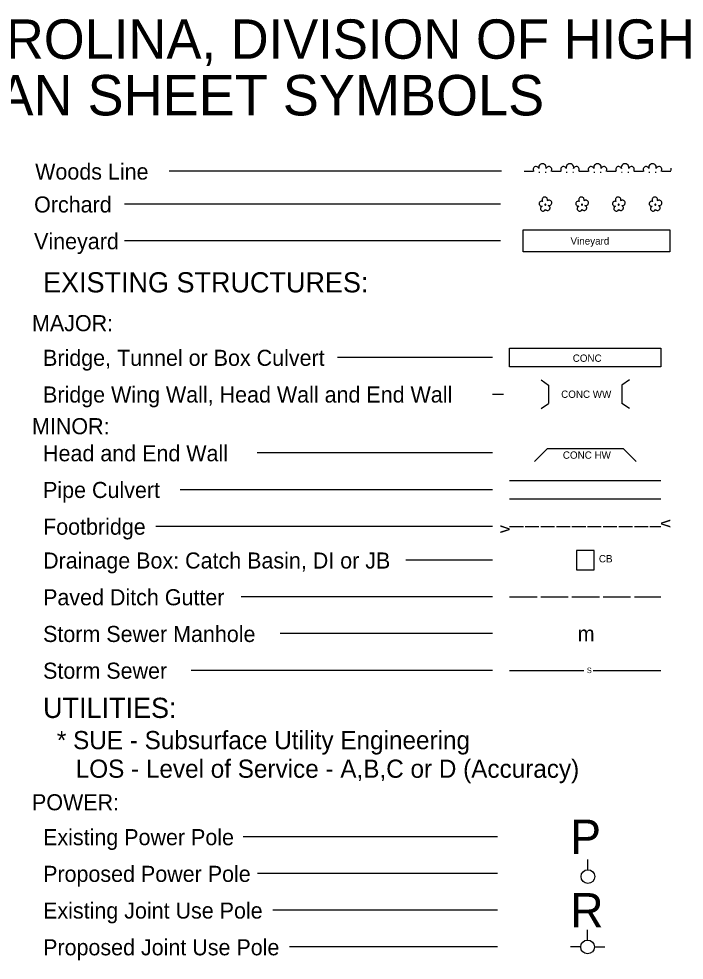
# Model space of a CAD drawing. Extents: x 2058324 to 2059808, y 675202 to 676238.
# Drawn here: x 2059088 to 2059451, y 675725 to 676238 of the extents above; entities that cross this region are included whole.
import ezdxf

# ---------------------------------------------------------------- set-up
doc = ezdxf.new("R2010")
doc.units = 0
doc.layers.add('Sheet Symbology CELL', color=7, linetype='Continuous')

msp = doc.modelspace()

# ---------------------------------------------------------------- linework, layer by layer
at = {"layer": 'Sheet Symbology CELL'}
for p, q in [((2059351.11, 676154.81), (2059169.98, 676154.81)), ((2059363.5, 676154.81), (2059368.5, 676154.81)), ((2059378.5, 676154.81), (2059383.5, 676154.81)), ((2059393.5, 676154.81), (2059398.5, 676154.81)), ((2059408.5, 676154.81), (2059413.5, 676154.81)), ((2059423.5, 676154.81), (2059428.5, 676154.81)), ((2059438.5, 676154.81), (2059443.5, 676154.81)), ((2059371.45, 676154.31), (2059371.95, 676154.31)), ((2059374.95, 676154.31), (2059375.45, 676154.31)), ((2059386.45, 676154.31), (2059386.95, 676154.31)), ((2059389.95, 676154.31), (2059390.45, 676154.31)), ((2059401.45, 676154.31), (2059401.95, 676154.31)), ((2059404.95, 676154.31), (2059405.45, 676154.31)), ((2059416.45, 676154.31), (2059416.95, 676154.31)), ((2059419.95, 676154.31), (2059420.45, 676154.31)), ((2059431.45, 676154.31), (2059431.95, 676154.31)), ((2059434.95, 676154.31), (2059435.45, 676154.31)), ((2059350.54, 676136.88), (2059145.6, 676136.88)), ((2059350.54, 676116.88), (2059145.6, 676116.88)), ((2059346.23, 676053.38), (2059261.8, 676053.38)), ((2059372.68, 676041.24), (2059376.78, 676038.38)), ((2059376.78, 676038.38), (2059376.78, 676028.38)), ((2059420.88, 676041.24), (2059416.78, 676038.38)), ((2059416.78, 676038.38), (2059416.78, 676028.38)), ((2059346.23, 676033.38), (2059352.21, 676033.38)), ((2059372.68, 676025.52), (2059376.78, 676028.38)), ((2059420.88, 676025.52), (2059416.78, 676028.38)), ((2059346.23, 676001.38), (2059217.93, 676001.38)), ((2059369.08, 675996.81), (2059376.15, 676003.88)), ((2059376.15, 676003.88), (2059417.4, 676003.88)), ((2059417.4, 676003.88), (2059424.48, 675996.81)), ((2059355.53, 675986.38), (2059438.03, 675986.38)), ((2059346.23, 675981.38), (2059176.04, 675981.38)), ((2059355.53, 675976.38), (2059438.03, 675976.38)), ((2059346.23, 675961.38), (2059162.75, 675961.38)), ((2059355.53, 675961.38), (2059363.03, 675961.38)), ((2059364.03, 675961.38), (2059371.53, 675961.38)), ((2059372.53, 675961.38), (2059380.03, 675961.38)), ((2059381.03, 675961.38), (2059388.53, 675961.38)), ((2059389.53, 675961.38), (2059397.03, 675961.38)), ((2059398.03, 675961.38), (2059405.53, 675961.38)), ((2059406.53, 675961.38), (2059414.03, 675961.38)), ((2059415.03, 675961.38), (2059422.53, 675961.38)), ((2059423.53, 675961.38), (2059431.03, 675961.38)), ((2059432.03, 675961.38), (2059438.03, 675961.38)), ((2059346.23, 675942.95), (2059299.03, 675942.95)), ((2059346.23, 675922.95), (2059209.28, 675922.95)), ((2059355.53, 675922.95), (2059370.53, 675922.95)), ((2059372.53, 675922.95), (2059387.53, 675922.95)), ((2059389.53, 675922.95), (2059404.53, 675922.95)), ((2059406.53, 675922.95), (2059421.53, 675922.95)), ((2059423.53, 675922.95), (2059438.03, 675922.95)), ((2059346.23, 675902.95), (2059230.55, 675902.95)), ((2059346.23, 675882.95), (2059182.03, 675882.95)), ((2059355.53, 675882.95), (2059396.05, 675882.95)), ((2059401.05, 675882.95), (2059438.03, 675882.95)), ((2059349.01, 675792.27), (2059210.31, 675792.27)), ((2059398.24, 675774.38), (2059398.24, 675780)), ((2059349.01, 675772.27), (2059218.1, 675772.27)), ((2059349.01, 675752.27), (2059226.5, 675752.27)), ((2059398.03, 675736.03), (2059398.03, 675741.65)), ((2059349.01, 675732.27), (2059235.5, 675732.27)), ((2059394.28, 675732.28), (2059388.65, 675732.28)), ((2059401.78, 675732.28), (2059407.4, 675732.28))]:
    msp.add_line(p, q, dxfattribs=at)
for points in [[(2059375.98, 676138.63), (2059376.13, 676138.93), (2059376.18, 676139.23), (2059376.13, 676139.53), (2059376.08, 676139.83), (2059375.93, 676140.08), (2059375.78, 676140.33), (2059375.53, 676140.53), (2059375.28, 676140.68), (2059374.93, 676140.78), (2059374.68, 676140.78), (2059374.38, 676140.73), (2059374.08, 676140.63), (2059373.83, 676140.48), (2059373.58, 676140.28), (2059373.43, 676139.98), (2059373.33, 676139.73), (2059373.28, 676139.43), (2059373.28, 676139.13), (2059373.33, 676138.83), (2059373.48, 676138.58), (2059373.68, 676138.28), (2059373.43, 676138.43), (2059373.13, 676138.48), (2059372.83, 676138.48), (2059372.58, 676138.38), (2059372.33, 676138.28), (2059372.08, 676138.08), (2059371.88, 676137.88), (2059371.73, 676137.63), (2059371.68, 676137.38), (2059371.63, 676137.03), (2059371.68, 676136.78), (2059371.78, 676136.53), (2059371.98, 676136.28), (2059372.13, 676136.08), (2059372.38, 676135.93), (2059372.68, 676135.78), (2059372.93, 676135.73), (2059373.23, 676135.73), (2059372.98, 676135.63), (2059372.73, 676135.43), (2059372.58, 676135.23), (2059372.48, 676134.93), (2059372.38, 676134.63), (2059372.38, 676134.38), (2059372.43, 676134.08), (2059372.58, 676133.83), (2059372.73, 676133.58), (2059372.93, 676133.38), (2059373.18, 676133.23), (2059373.43, 676133.13), (2059373.73, 676133.13), (2059374.03, 676133.13), (2059374.28, 676133.18), (2059374.53, 676133.38), (2059374.78, 676133.53), (2059375.03, 676133.98)], [(2059375.03, 676133.98), (2059375.63, 676133.63), (2059375.93, 676133.53), (2059376.23, 676133.48), (2059376.53, 676133.53), (2059376.78, 676133.63), (2059377.03, 676133.78), (2059377.28, 676133.98), (2059377.43, 676134.23), (2059377.53, 676134.48), (2059377.63, 676134.78), (2059377.58, 676135.08), (2059377.53, 676135.38), (2059377.33, 676135.68), (2059377.18, 676135.88), (2059376.93, 676136.03), (2059376.63, 676136.18), (2059376.93, 676136.13), (2059377.28, 676136.13), (2059377.53, 676136.23), (2059377.83, 676136.38), (2059378.08, 676136.53), (2059378.28, 676136.78), (2059378.43, 676137.08), (2059378.48, 676137.38), (2059378.53, 676137.68), (2059378.48, 676137.98), (2059378.38, 676138.28), (2059378.18, 676138.53), (2059377.93, 676138.78), (2059377.68, 676138.93), (2059377.38, 676139.03), (2059377.08, 676139.08), (2059376.78, 676139.08), (2059376.48, 676138.98), (2059376.23, 676138.83), (2059375.98, 676138.63)], [(2059395.98, 676138.63), (2059396.13, 676138.93), (2059396.18, 676139.23), (2059396.13, 676139.53), (2059396.08, 676139.83), (2059395.93, 676140.08), (2059395.78, 676140.33), (2059395.53, 676140.53), (2059395.28, 676140.68), (2059394.93, 676140.78), (2059394.68, 676140.78), (2059394.38, 676140.73), (2059394.08, 676140.63), (2059393.83, 676140.48), (2059393.58, 676140.28), (2059393.43, 676139.98), (2059393.33, 676139.73), (2059393.28, 676139.43), (2059393.28, 676139.13), (2059393.33, 676138.83), (2059393.48, 676138.58), (2059393.68, 676138.28), (2059393.43, 676138.43), (2059393.13, 676138.48), (2059392.83, 676138.48), (2059392.58, 676138.38), (2059392.33, 676138.28), (2059392.08, 676138.08), (2059391.88, 676137.88), (2059391.73, 676137.63), (2059391.68, 676137.38), (2059391.63, 676137.03), (2059391.68, 676136.78), (2059391.78, 676136.53), (2059391.98, 676136.28), (2059392.13, 676136.08), (2059392.38, 676135.93), (2059392.68, 676135.78), (2059392.93, 676135.73), (2059393.23, 676135.73), (2059392.98, 676135.63), (2059392.73, 676135.43), (2059392.58, 676135.23), (2059392.48, 676134.93), (2059392.38, 676134.63), (2059392.38, 676134.38), (2059392.43, 676134.08), (2059392.58, 676133.83), (2059392.73, 676133.58), (2059392.93, 676133.38), (2059393.18, 676133.23), (2059393.43, 676133.13), (2059393.73, 676133.13), (2059394.03, 676133.13), (2059394.28, 676133.18), (2059394.53, 676133.38), (2059394.78, 676133.53), (2059395.03, 676133.98)], [(2059395.03, 676133.98), (2059395.63, 676133.63), (2059395.93, 676133.53), (2059396.23, 676133.48), (2059396.53, 676133.53), (2059396.78, 676133.63), (2059397.03, 676133.78), (2059397.28, 676133.98), (2059397.43, 676134.23), (2059397.53, 676134.48), (2059397.63, 676134.78), (2059397.58, 676135.08), (2059397.53, 676135.38), (2059397.33, 676135.68), (2059397.18, 676135.88), (2059396.93, 676136.03), (2059396.63, 676136.18), (2059396.93, 676136.13), (2059397.28, 676136.13), (2059397.53, 676136.23), (2059397.83, 676136.38), (2059398.08, 676136.53), (2059398.28, 676136.78), (2059398.43, 676137.08), (2059398.48, 676137.38), (2059398.53, 676137.68), (2059398.48, 676137.98), (2059398.38, 676138.28), (2059398.18, 676138.53), (2059397.93, 676138.78), (2059397.68, 676138.93), (2059397.38, 676139.03), (2059397.08, 676139.08), (2059396.78, 676139.08), (2059396.48, 676138.98), (2059396.23, 676138.83), (2059395.98, 676138.63)], [(2059415.98, 676138.63), (2059416.13, 676138.93), (2059416.18, 676139.23), (2059416.13, 676139.53), (2059416.08, 676139.83), (2059415.93, 676140.08), (2059415.78, 676140.33), (2059415.53, 676140.53), (2059415.28, 676140.68), (2059414.93, 676140.78), (2059414.68, 676140.78), (2059414.38, 676140.73), (2059414.08, 676140.63), (2059413.83, 676140.48), (2059413.58, 676140.28), (2059413.43, 676139.98), (2059413.33, 676139.73), (2059413.28, 676139.43), (2059413.28, 676139.13), (2059413.33, 676138.83), (2059413.48, 676138.58), (2059413.68, 676138.28), (2059413.43, 676138.43), (2059413.13, 676138.48), (2059412.83, 676138.48), (2059412.58, 676138.38), (2059412.33, 676138.28), (2059412.08, 676138.08), (2059411.88, 676137.88), (2059411.73, 676137.63), (2059411.68, 676137.38), (2059411.63, 676137.03), (2059411.68, 676136.78), (2059411.78, 676136.53), (2059411.98, 676136.28), (2059412.13, 676136.08), (2059412.38, 676135.93), (2059412.68, 676135.78), (2059412.93, 676135.73), (2059413.23, 676135.73), (2059412.98, 676135.63), (2059412.73, 676135.43), (2059412.58, 676135.23), (2059412.48, 676134.93), (2059412.38, 676134.63), (2059412.38, 676134.38), (2059412.43, 676134.08), (2059412.58, 676133.83), (2059412.73, 676133.58), (2059412.93, 676133.38), (2059413.18, 676133.23), (2059413.43, 676133.13), (2059413.73, 676133.13), (2059414.03, 676133.13), (2059414.28, 676133.18), (2059414.53, 676133.38), (2059414.78, 676133.53), (2059415.03, 676133.98)], [(2059415.03, 676133.98), (2059415.63, 676133.63), (2059415.93, 676133.53), (2059416.23, 676133.48), (2059416.53, 676133.53), (2059416.78, 676133.63), (2059417.03, 676133.78), (2059417.28, 676133.98), (2059417.43, 676134.23), (2059417.53, 676134.48), (2059417.63, 676134.78), (2059417.58, 676135.08), (2059417.53, 676135.38), (2059417.33, 676135.68), (2059417.18, 676135.88), (2059416.93, 676136.03), (2059416.63, 676136.18), (2059416.93, 676136.13), (2059417.28, 676136.13), (2059417.53, 676136.23), (2059417.83, 676136.38), (2059418.08, 676136.53), (2059418.28, 676136.78), (2059418.43, 676137.08), (2059418.48, 676137.38), (2059418.53, 676137.68), (2059418.48, 676137.98), (2059418.38, 676138.28), (2059418.18, 676138.53), (2059417.93, 676138.78), (2059417.68, 676138.93), (2059417.38, 676139.03), (2059417.08, 676139.08), (2059416.78, 676139.08), (2059416.48, 676138.98), (2059416.23, 676138.83), (2059415.98, 676138.63)], [(2059435.98, 676138.63), (2059436.13, 676138.93), (2059436.18, 676139.23), (2059436.13, 676139.53), (2059436.08, 676139.83), (2059435.93, 676140.08), (2059435.78, 676140.33), (2059435.53, 676140.53), (2059435.28, 676140.68), (2059434.93, 676140.78), (2059434.68, 676140.78), (2059434.38, 676140.73), (2059434.08, 676140.63), (2059433.83, 676140.48), (2059433.58, 676140.28), (2059433.43, 676139.98), (2059433.33, 676139.73), (2059433.28, 676139.43), (2059433.28, 676139.13), (2059433.33, 676138.83), (2059433.48, 676138.58), (2059433.68, 676138.28), (2059433.43, 676138.43), (2059433.13, 676138.48), (2059432.83, 676138.48), (2059432.58, 676138.38), (2059432.33, 676138.28), (2059432.08, 676138.08), (2059431.88, 676137.88), (2059431.73, 676137.63), (2059431.68, 676137.38), (2059431.63, 676137.03), (2059431.68, 676136.78), (2059431.78, 676136.53), (2059431.98, 676136.28), (2059432.13, 676136.08), (2059432.38, 676135.93), (2059432.68, 676135.78), (2059432.93, 676135.73), (2059433.23, 676135.73), (2059432.98, 676135.63), (2059432.73, 676135.43), (2059432.58, 676135.23), (2059432.48, 676134.93), (2059432.38, 676134.63), (2059432.38, 676134.38), (2059432.43, 676134.08), (2059432.58, 676133.83), (2059432.73, 676133.58), (2059432.93, 676133.38), (2059433.18, 676133.23), (2059433.43, 676133.13), (2059433.73, 676133.13), (2059434.03, 676133.13), (2059434.28, 676133.18), (2059434.53, 676133.38), (2059434.78, 676133.53), (2059435.03, 676133.98)], [(2059435.03, 676133.98), (2059435.63, 676133.63), (2059435.93, 676133.53), (2059436.23, 676133.48), (2059436.53, 676133.53), (2059436.78, 676133.63), (2059437.03, 676133.78), (2059437.28, 676133.98), (2059437.43, 676134.23), (2059437.53, 676134.48), (2059437.63, 676134.78), (2059437.58, 676135.08), (2059437.53, 676135.38), (2059437.33, 676135.68), (2059437.18, 676135.88), (2059436.93, 676136.03), (2059436.63, 676136.18), (2059436.93, 676136.13), (2059437.28, 676136.13), (2059437.53, 676136.23), (2059437.83, 676136.38), (2059438.08, 676136.53), (2059438.28, 676136.78), (2059438.43, 676137.08), (2059438.48, 676137.38), (2059438.53, 676137.68), (2059438.48, 676137.98), (2059438.38, 676138.28), (2059438.18, 676138.53), (2059437.93, 676138.78), (2059437.68, 676138.93), (2059437.38, 676139.03), (2059437.08, 676139.08), (2059436.78, 676139.08), (2059436.48, 676138.98), (2059436.23, 676138.83), (2059435.98, 676138.63)], [(2059375.13, 676136.88), (2059374.98, 676136.88), (2059374.88, 676136.83), (2059374.78, 676136.78), (2059374.78, 676136.63), (2059374.78, 676136.53), (2059374.88, 676136.43), (2059375.03, 676136.43), (2059375.13, 676136.43), (2059375.23, 676136.53), (2059375.28, 676136.68), (2059375.23, 676136.78), (2059375.13, 676136.88)], [(2059395.13, 676136.88), (2059394.98, 676136.88), (2059394.88, 676136.83), (2059394.78, 676136.78), (2059394.78, 676136.63), (2059394.78, 676136.53), (2059394.88, 676136.43), (2059395.03, 676136.43), (2059395.13, 676136.43), (2059395.23, 676136.53), (2059395.28, 676136.68), (2059395.23, 676136.78), (2059395.13, 676136.88)], [(2059415.13, 676136.88), (2059414.98, 676136.88), (2059414.88, 676136.83), (2059414.78, 676136.78), (2059414.78, 676136.63), (2059414.78, 676136.53), (2059414.88, 676136.43), (2059415.03, 676136.43), (2059415.13, 676136.43), (2059415.23, 676136.53), (2059415.28, 676136.68), (2059415.23, 676136.78), (2059415.13, 676136.88)], [(2059435.13, 676136.88), (2059434.98, 676136.88), (2059434.88, 676136.83), (2059434.78, 676136.78), (2059434.78, 676136.63), (2059434.78, 676136.53), (2059434.88, 676136.43), (2059435.03, 676136.43), (2059435.13, 676136.43), (2059435.23, 676136.53), (2059435.28, 676136.68), (2059435.23, 676136.78), (2059435.13, 676136.88)], [(2059362.93, 676122.88), (2059442.93, 676122.88), (2059442.93, 676110.88), (2059362.93, 676110.88), (2059362.93, 676122.88)], [(2059355.53, 676058.38), (2059438.03, 676058.38), (2059438.03, 676048.38), (2059355.53, 676048.38), (2059355.53, 676058.38)]]:
    msp.add_lwpolyline(points, dxfattribs=at)
msp.add_lwpolyline([(2059391.96, 675937.63), (2059401.58, 675937.63), (2059401.58, 675948.27), (2059391.96, 675948.27)], close=True, dxfattribs=at)
for centre in [(2059398.24, 675770.63), (2059398.03, 675732.27)]:
    msp.add_circle(centre, 3.75, dxfattribs=at)
for centre, radius, start, end in [((2059369.95, 676155.83), 1.58, 18.4349, 219.2315), ((2059373.45, 676156.83), 2.06, 345.9638, 194.0362), ((2059376.95, 676155.83), 1.58, 320.7685, 161.565), ((2059384.95, 676155.83), 1.58, 18.4349, 219.2315), ((2059388.45, 676156.83), 2.06, 345.9638, 194.0362), ((2059391.95, 676155.83), 1.58, 320.7685, 161.565), ((2059399.95, 676155.83), 1.58, 18.4349, 219.2315), ((2059403.45, 676156.83), 2.06, 345.9638, 194.0362), ((2059406.95, 676155.83), 1.58, 320.7685, 161.565), ((2059414.95, 676155.83), 1.58, 18.4349, 219.2315), ((2059418.45, 676156.83), 2.06, 345.9638, 194.0362), ((2059421.95, 676155.83), 1.58, 320.7685, 161.565), ((2059429.95, 676155.83), 1.58, 18.4349, 219.2315), ((2059433.45, 676156.83), 2.06, 345.9638, 194.0362), ((2059436.95, 676155.83), 1.58, 320.7685, 161.565), ((2059444.95, 676155.83), 1.58, 156.251, 203.749)]:
    msp.add_arc(centre, radius, start, end, dxfattribs=at)

# ---------------------------------------------------------------- texts
for s, height, rotation, p in [('STATE OF NORTH CAROLINA, DIVISION OF HIGHWAYS', 21.419, 360, (2058783.41, 676216.12)), ('CONVENTIONAL  PLAN SHEET SYMBOLS', 22.0323, 360, (2058791.54, 676185.24)), ('Woods Line', 8.75, 360, (2059096.95, 676150.29)), ('Orchard', 8.75, 360, (2059096.38, 676132.36)), ('Vineyard', 8.75, 360, (2059096.38, 676112.36)), ('Vineyard', 4, 0, (2059388.76, 676114.88)), ('EXISTING STRUCTURES:', 11, 360, (2059101.26, 676088.83)), ('MAJOR:', 8.75, 360, (2059095.24, 676067.71)), ('Bridge, Tunnel or Box Culvert', 8.75, 360, (2059101.26, 676048.83)), ('CONC', 4, 360, (2059389.96, 676051.02)), ('Bridge Wing Wall, Head Wall and End Wall', 8.75, 360, (2059101.26, 676028.83)), ('CONC WW', 4, 0, (2059383.65, 676031.38)), ('MINOR:', 8.75, 360, (2059095.24, 676011.59)), ('Head and End Wall', 8.75, 360, (2059101.26, 675996.83)), ('CONC HW', 4, 360, (2059384.58, 675998.22)), ('Pipe Culvert', 8.75, 360, (2059101.26, 675976.85)), ('Footbridge', 8.75, 360, (2059101.28, 675956.85)), ('v', 6.6, 270.2409, (2059438.01, 675965.12)), ('v', 6.6, 89.7591, (2059355.51, 675957.65)), ('Drainage Box: Catch Basin, DI or JB', 8.75, 360, (2059101.28, 675938.41)), ('CB', 4, 360, (2059404.21, 675941.77)), ('Paved Ditch Gutter', 8.75, 360, (2059101.28, 675918.4)), ('Storm Sewer Manhole', 8.75, 360, (2059101.28, 675898.4)), ('m', 8.25, 360, (2059392.65, 675898.82)), ('Storm Sewer', 8.75, 360, (2059101.28, 675878.4)), ('S', 3, 360, (2059397.65, 675881.45)), ('UTILITIES:', 11, 360, (2059101.26, 675857.03)), ('* SUE - Subsurface Utility Engineering', 9.9, 360, (2059108.8, 675840.01)), ('LOS - Level of Service - A,B,C or D (Accuracy) ', 9.9, 360, (2059119.07, 675824.44)), ('POWER:', 8.75, 360, (2059095.24, 675806.73)), ('P', 18.75, 360, (2059388.65, 675782.89)), ('Existing Power Pole', 8.75, 360, (2059101.28, 675787.73)), ('Proposed Power Pole', 8.75, 360, (2059101.28, 675767.73)), ('R', 18.75, 360, (2059388.65, 675742.89)), ('Existing Joint Use Pole', 8.75, 360, (2059101.28, 675747.74)), ('Proposed Joint Use Pole', 8.75, 360, (2059101.29, 675727.73))]:
    msp.add_text(s, height=height, rotation=rotation, dxfattribs=at).set_placement(p)

doc.saveas('drawing.dxf')
